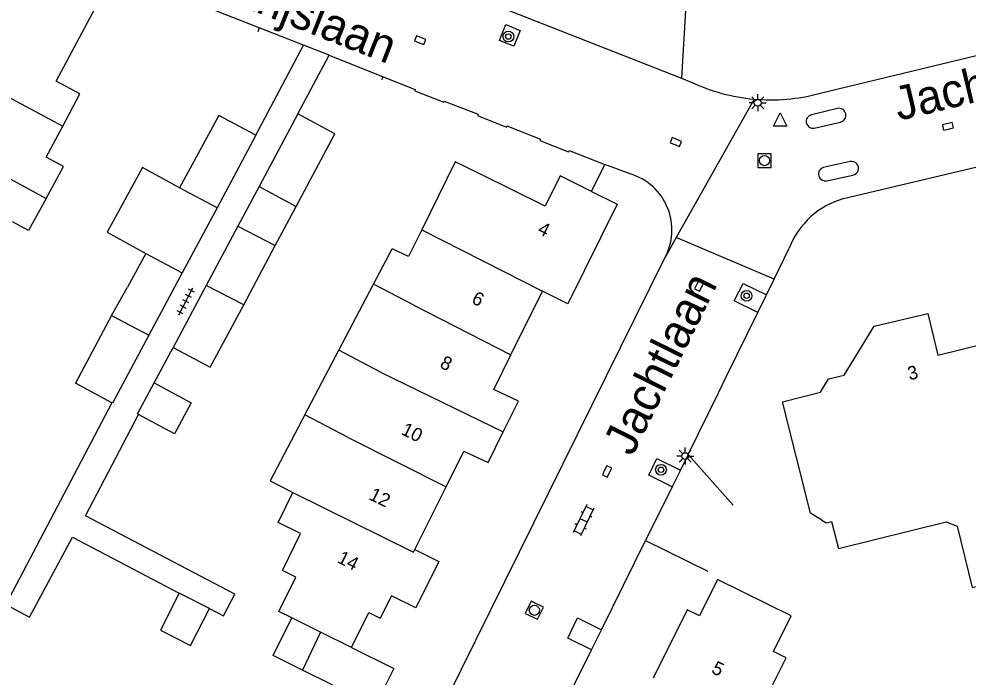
# Model space of a CAD drawing. Extents: x 136000 to 141000, y 400494 to 402006.
# Drawn here: x 137841.5 to 137911.7, y 401638.7 to 401687.4 of the extents above; entities that cross this region are included whole.
import ezdxf

# ---------------------------------------------------------------- set-up
doc = ezdxf.new("R2010")
doc.units = 0
for name, color, linetype in [('gg-afsc-erfafscheiding', 7, 'Continuous'), ('gg-afsc-muur', 7, 'Continuous'), ('gg-anno-huisnummerreeks BGT', 7, 'Continuous'), ('gg-anno-openbare ruimte label', 7, 'Continuous'), ('gg-bbg-bijgebouw', 7, 'Continuous'), ('gg-bbg-gedigitaliseerde bebouwing', 7, 'Continuous'), ('gg-bbg-gedigitaliseerde bijgebouw', 7, 'Continuous'), ('gg-bbg-hoofdgebouw', 7, 'Continuous'), ('gg-bbg-tussenscheiding', 7, 'Continuous'), ('gg-knt-verharding', 7, 'Continuous'), ('gt-grn-weggrens', 7, 'Continuous'), ('gt-symb-boom', 7, 'Continuous'), ('gt-symb-klinker verharding', 7, 'Continuous'), ('gt-symb-kolk', 7, 'Continuous'), ('gt-symb-lichtmast', 7, 'Continuous'), ('gt-symb-rioolschacht', 7, 'Continuous'), ('gt-symb-tegel verharding', 7, 'Continuous'), ('gt-symb-waterafsluiter', 7, 'Continuous')]:
    doc.layers.add(name, color=color, linetype=linetype)

# ---------------------------------------------------------------- blocks, each defined once
blk = doc.blocks.new('gt0-KOLK')
at = {"layer": 'gt-symb-kolk'}
blk.add_lwpolyline([(0, 0), (0.375, 0), (0.375, 0.4), (-0.375, 0.4), (-0.375, 0), (0, 0)], dxfattribs=at)
blk = doc.blocks.new('gt0-BOOM')
at = {"layer": 'gt-symb-boom'}
for radius in [0.4, 0.2]:
    blk.add_circle((0, 0), radius, dxfattribs=at)
blk = doc.blocks.new('gt0-LMAST')
at = {"layer": 'gt-symb-lichtmast'}
for p, q in [((-0.182, 0.173), (-0.447, 0.438)), ((-0.005, 0.246), (-0.005, 0.621)), ((0.172, 0.173), (0.437, 0.438)), ((-0.255, -0.004), (-0.63, -0.004)), ((-0.182, -0.181), (-0.447, -0.446)), ((-0.005, -0.254), (-0.005, -0.629)), ((0.437, -0.446), (0.172, -0.181)), ((0.245, -0.004), (0.62, -0.004))]:
    blk.add_line(p, q, dxfattribs=at)
blk.add_circle((-0.005, -0.004), 0.25, dxfattribs=at)
blk = doc.blocks.new('gt0-RS')
at = {"layer": 'gt-symb-rioolschacht'}
blk.add_lwpolyline([(-0.5, -0.5), (0.5, -0.5), (0.5, 0.5), (-0.5, 0.5)], close=True, dxfattribs=at)
blk.add_circle((0, 0), 0.375, dxfattribs=at)
blk = doc.blocks.new('gt0-WAFSL')
at = {"layer": 'gt-symb-waterafsluiter'}
for p, q in [((-0.5, -0.333), (0, 0.667)), ((0, 0.667), (0.5, -0.333)), ((0.5, -0.333), (-0.5, -0.333))]:
    blk.add_line(p, q, dxfattribs=at)
blk = doc.blocks.new('gt0-TEG1')
at = {"layer": 'gt-symb-tegel verharding'}
for p, q in [((-1.125, 0), (1.125, 0)), ((-0.9, -0.25), (-0.9, 0.25)), ((-0.45, -0.25), (-0.45, 0.25)), ((0, -0.25), (0, 0.25)), ((0.45, -0.25), (0.45, 0.25)), ((0.9, -0.25), (0.9, 0.25))]:
    blk.add_line(p, q, dxfattribs=at)
blk = doc.blocks.new('gt0-KL1')
at = {"layer": 'gt-symb-klinker verharding'}
for p, q in [((-1.15, 0.3), (1.15, 0.3)), ((-1, -0.3), (-1, 0.3)), ((-0.5, 0.3), (-0.5, 0.45)), ((0, -0.3), (0, 0.3)), ((0.5, 0.3), (0.5, 0.45)), ((1, -0.3), (1, 0.3)), ((-1.15, -0.3), (1.15, -0.3)), ((-0.5, -0.45), (-0.5, -0.3)), ((0.5, -0.45), (0.5, -0.3))]:
    blk.add_line(p, q, dxfattribs=at)

msp = doc.modelspace()

# ---------------------------------------------------------------- linework, layer by layer
at = {"layer": 'gg-afsc-erfafscheiding'}
for points in [[(137882.227, 401714.91), (137892.182, 401711.001), (137890.525, 401682.979)], [(137848.387, 401658.961), (137840.554, 401644.032), (137842.304, 401643.095), (137845.475, 401649.014), (137853.375, 401644.869)], [(137855.605, 401643.731), (137856.639, 401643.188), (137857.48, 401644.79), (137846.428, 401650.589), (137850.362, 401658.085)]]:
    msp.add_lwpolyline(points, dxfattribs=at)
at = {"layer": 'gg-afsc-muur'}
for p, q in [((137859.293, 401686.702), (137839.536, 401694.481)), ((137859.293, 401686.702), (137859.184, 401686.405)), ((137859.039, 401678.757), (137862.567, 401685.415)), ((137862.139, 401680.33), (137864.457, 401684.672)), ((137864.457, 401684.672), (137868.45, 401683.081)), ((137868.45, 401683.081), (137868.459, 401683.106)), ((137868.378, 401682.873), (137868.45, 401683.081)), ((137868.45, 401683.081), (137870.839, 401682.13)), ((137883.887, 401674.594), (137884.872, 401676.588)), ((137851.509, 401660.425), (137852.921, 401663.059)), ((137891.038, 401655.14), (137890.456, 401653.969)), ((137894.351, 401651.395), (137891.038, 401655.14)), ((137890.456, 401653.969), (137889.85, 401652.751)), ((137889.85, 401652.751), (137887.866, 401648.763)), ((137887.866, 401648.763), (137892.495, 401646.498))]:
    msp.add_line(p, q, dxfattribs=at)
msp.add_lwpolyline([(137870.839, 401682.13), (137870.799, 401682.032), (137872.948, 401681.197), (137872.981, 401681.282), (137875.482, 401680.305), (137875.444, 401680.207), (137877.583, 401679.363), (137877.621, 401679.448), (137880.096, 401678.456), (137880.057, 401678.359), (137882.183, 401677.533), (137882.221, 401677.63), (137884.872, 401676.588)], dxfattribs=at)
at = {"layer": 'gg-bbg-bijgebouw'}
for p, q in [((137862.139, 401680.33), (137859.277, 401674.968)), ((137859.039, 401678.757), (137856.299, 401680.225)), ((137859.039, 401678.757), (137856.169, 401673.396)), ((137859.277, 401674.968), (137857.704, 401672.02)), ((137856.169, 401673.396), (137853.594, 401668.584)), ((137860.479, 401670.591), (137862.017, 401673.474)), ((137857.704, 401672.02), (137855.368, 401667.643)), ((137858.142, 401666.215), (137860.479, 401670.591)), ((137853.594, 401668.584), (137851.115, 401663.952)), ((137855.368, 401667.643), (137852.921, 401663.059)), ((137848.387, 401658.961), (137845.689, 401660.406))]:
    msp.add_line(p, q, dxfattribs=at)
for points in [[(137862.017, 401673.474), (137864.894, 401678.862), (137862.139, 401680.33)], [(137852.921, 401663.059), (137855.673, 401661.59), (137858.142, 401666.215)], [(137851.115, 401663.952), (137848.431, 401658.938), (137848.387, 401658.961)], [(137850.362, 401658.085), (137850.275, 401658.132), (137851.509, 401660.425)], [(137851.509, 401660.425), (137854.256, 401658.946), (137853.022, 401656.653), (137850.362, 401658.085)]]:
    msp.add_lwpolyline(points, dxfattribs=at)
at = {"layer": 'gg-bbg-gedigitaliseerde bebouwing'}
for p, q in [((137844.758, 401679.427), (137846.028, 401681.809)), ((137867.745, 401667.741), (137869.12, 401670.362)), ((137865.177, 401662.846), (137867.745, 401667.741)), ((137862.666, 401658.061), (137865.177, 401662.846)), ((137867.88, 401636.53), (137862.501, 401639.178))]:
    msp.add_line(p, q, dxfattribs=at)
for points in [[(137843.52, 401674.064), (137844.821, 401676.433), (137843.521, 401677.144), (137844.758, 401679.427)], [(137843.52, 401674.064), (137842.219, 401671.695), (137841.025, 401672.351)], [(137900.916, 401650.273), (137901.238, 401650.079), (137901.643, 401650.18), (137902.146, 401648.168), (137910.128, 401650.16), (137910.92, 401649.827), (137912.05, 401645.298), (137916.963, 401646.524), (137912.91, 401663.31)], [(137862.666, 401658.061), (137860.109, 401653.187), (137861.78, 401652.31)], [(137861.697, 401643.052), (137860.753, 401643.52), (137862.009, 401646.056), (137861.004, 401646.554), (137862.354, 401649.28), (137860.688, 401650.105), (137861.78, 401652.31)], [(137899.176, 401633.249), (137899.317, 401633.533), (137897.73, 401634.319), (137898.79, 401636.46), (137896.928, 401637.382), (137898.271, 401640.097), (137897.338, 401640.559), (137898.64, 401643.188), (137893.2, 401645.89)]]:
    msp.add_lwpolyline(points, dxfattribs=at)
at = {"layer": 'gg-bbg-gedigitaliseerde bijgebouw'}
for p, q in [((137856.299, 401680.225), (137853.384, 401674.868)), ((137850.907, 401670.007), (137849.539, 401667.516)), ((137848.355, 401665.426), (137849.539, 401667.516)), ((137848.355, 401665.426), (137845.689, 401660.406)), ((137855.605, 401643.731), (137853.375, 401644.869))]:
    msp.add_line(p, q, dxfattribs=at)
for points in [[(137853.384, 401674.868), (137850.668, 401676.36), (137848.043, 401671.58), (137850.907, 401670.007)], [(137853.375, 401644.869), (137851.985, 401642.144), (137854.215, 401641.006), (137855.605, 401643.731)], [(137862.501, 401639.178), (137860.312, 401640.255), (137861.697, 401643.052)]]:
    msp.add_lwpolyline(points, dxfattribs=at)
at = {"layer": 'gg-bbg-hoofdgebouw'}
for p, q in [((137880.44, 401673.507), (137875.62, 401675.89)), ((137877.919, 401662.5), (137880.245, 401667.214)), ((137870.817, 401648.104), (137873.114, 401652.742)), ((137890.96, 401643.65), (137888.44, 401638.57))]:
    msp.add_line(p, q, dxfattribs=at)
for points in [[(137846.028, 401681.809), (137844.278, 401682.763), (137847.34, 401688.518), (137841.179, 401691.841), (137839.52, 401688.78)], [(137875.62, 401675.89), (137873.787, 401676.785), (137871.317, 401671.763)], [(137883.887, 401674.594), (137881.547, 401675.749), (137880.44, 401673.507)], [(137883.887, 401674.594), (137885.77, 401673.664), (137882.128, 401666.284), (137880.245, 401667.214)], [(137871.317, 401671.763), (137870.342, 401669.78), (137869.12, 401670.362)], [(137900.916, 401650.273), (137900.068, 401650.783), (137898.01, 401659.03), (137900.83, 401659.74), (137901.4, 401660.73), (137902.58, 401661), (137904.8, 401664.62), (137908.77, 401665.57), (137909.51, 401662.49), (137912.91, 401663.31)], [(137877.345, 401656.805), (137878.47, 401659.07), (137876.66, 401659.95), (137877.919, 401662.5)], [(137873.114, 401652.742), (137874.42, 401655.38), (137876.22, 401654.54), (137877.345, 401656.805)], [(137870.817, 401648.104), (137872.583, 401647.223), (137870.869, 401643.787), (137869.082, 401644.662), (137868.243, 401643.023)], [(137893.2, 401645.89), (137891.86, 401643.2), (137890.96, 401643.65)], [(137866.109, 401640.857), (137867.4, 401643.44), (137868.243, 401643.023)], [(137866.109, 401640.857), (137869.24, 401639.3), (137867.88, 401636.53)]]:
    msp.add_lwpolyline(points, dxfattribs=at)
at = {"layer": 'gg-bbg-tussenscheiding'}
for p, q in [((137835.959, 401684.148), (137844.758, 401679.427)), ((137840.594, 401675.671), (137843.52, 401674.064)), ((137856.169, 401673.396), (137853.384, 401674.868)), ((137859.277, 401674.968), (137862.017, 401673.474)), ((137857.704, 401672.02), (137860.479, 401670.591)), ((137871.317, 401671.763), (137880.245, 401667.214)), ((137850.907, 401670.007), (137853.594, 401668.584)), ((137870.721, 401666.18), (137867.745, 401667.741)), ((137858.142, 401666.215), (137855.368, 401667.643)), ((137870.721, 401666.18), (137877.919, 401662.5)), ((137848.355, 401665.426), (137851.115, 401663.952)), ((137868.267, 401661.224), (137865.177, 401662.846)), ((137868.267, 401661.224), (137877.345, 401656.805)), ((137865.869, 401656.38), (137862.666, 401658.061)), ((137865.869, 401656.38), (137873.114, 401652.742)), ((137863.824, 401641.994), (137861.697, 401643.052)), ((137863.824, 401641.994), (137862.501, 401639.178)), ((137866.109, 401640.857), (137863.824, 401641.994))]:
    msp.add_line(p, q, dxfattribs=at)
msp.add_lwpolyline([(137861.78, 401652.31), (137870.718, 401647.904), (137870.817, 401648.104)], dxfattribs=at)
at = {"layer": 'gg-knt-verharding'}
for p, q in [((137859.009, 401695.383), (137890.525, 401682.979)), ((137862.567, 401685.415), (137859.293, 401686.702)), ((137864.457, 401684.672), (137862.567, 401685.415)), ((137890.525, 401682.979), (137891.261, 401682.689)), ((137902.086, 401680.74), (137900.154, 401680.268)), ((137900.359, 401679.286), (137902.31, 401679.733)), ((137902.53, 401674.07), (137922.882, 401678.934)), ((137903.008, 401676.806), (137901.029, 401676.369)), ((137886.73, 401675.9), (137884.872, 401676.588)), ((137901.291, 401675.383), (137903.217, 401675.796)), ((137897.383, 401668.107), (137898.51, 401670.411)), ((137863.73, 401617.96), (137889.28, 401669.641)), ((137896.814, 401666.944), (137897.383, 401668.107)), ((137896.178, 401665.644), (137896.814, 401666.944)), ((137893.871, 401660.93), (137896.178, 401665.644)), ((137893.248, 401659.656), (137893.871, 401660.93)), ((137891.038, 401655.14), (137893.248, 401659.656)), ((137884.607, 401642.165), (137887.866, 401648.763)), ((137883.867, 401640.667), (137884.607, 401642.165)), ((137872.928, 401618.523), (137883.867, 401640.667))]:
    msp.add_line(p, q, dxfattribs=at)
for points in [[(137877.18, 401686.042), (137877.536, 401686.958), (137878.592, 401686.517), (137878.128, 401685.346), (137877.069, 401685.757), (137877.18, 401686.042)], [(137900.7, 401681.84), (137918.809, 401686.207), (137920.955, 401686.767)], [(137896.178, 401665.644), (137894.444, 401666.493), (137895.107, 401667.779), (137896.814, 401666.944)], [(137889.85, 401652.751), (137888.124, 401653.609), (137888.703, 401654.841), (137890.456, 401653.969)], [(137883.867, 401640.667), (137882.116, 401641.532), (137882.848, 401643.034), (137884.607, 401642.165)]]:
    msp.add_lwpolyline(points, dxfattribs=at)
for centre, radius, start, end in [((137897.143, 401695.191), 13.817, 244.80408, 264.85905), ((137897.142, 401695.207), 13.833, 264.86935, 284.90512), ((137902.184, 401680.233), 0.516, 284.11016, 100.97156), ((137900.26, 401679.778), 0.502, 102.24274, 281.34044), ((137903.117, 401676.302), 0.516, 281.21469, 102.1678), ((137901.178, 401675.881), 0.51, 107.01785, 282.74369), ((137885.508, 401671.753), 4.323, 330.75029, 73.58299), ((137904.215, 401668.181), 6.125, 105.96599, 158.65087)]:
    msp.add_arc(centre, radius, start, end, dxfattribs=at)
at = {"layer": 'gt-grn-weggrens'}
for p, q in [((137895.905, 401681.43), (137890.15, 401671.189)), ((137890.15, 401671.189), (137889.28, 401669.641)), ((137897.383, 401668.107), (137890.15, 401671.189))]:
    msp.add_line(p, q, dxfattribs=at)

# ---------------------------------------------------------------- block references
at = {"layer": 'gt-symb-boom'}
for p in [(137877.725, 401686.061), (137895.351, 401666.875), (137889.02, 401654.003)]:
    msp.add_blockref('gt0-BOOM', p, dxfattribs=at)
at = {"layer": 'gt-symb-klinker verharding', "rotation": -115.97571465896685}
msp.add_blockref('gt0-KL1', (137883.287, 401650.271), dxfattribs=at)
at = {"layer": 'gt-symb-kolk'}
for p, rotation in [((137871.131, 401685.598), -21.641900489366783), ((137910.296, 401679.214), 13.480126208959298), ((137890.041, 401678.067), -21.641900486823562), ((137891.676, 401667.732), -116.36005820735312), ((137884.849, 401653.961), -116.36005820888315)]:
    msp.add_blockref('gt0-KOLK', p, dxfattribs=dict(at, rotation=rotation))
at = {"layer": 'gt-symb-lichtmast'}
for p in [(137896.178, 401681.163), (137890.817, 401655.019)]:
    msp.add_blockref('gt0-LMAST', p, dxfattribs=at)
at = {"layer": 'gt-symb-rioolschacht'}
msp.add_blockref('gt0-RS', (137896.677, 401676.879), dxfattribs=at)
at = {"layer": 'gt-symb-rioolschacht', "rotation": 63.716687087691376}
msp.add_blockref('gt0-RS', (137879.65, 401643.605), dxfattribs=at)
at = {"layer": 'gt-symb-tegel verharding', "rotation": 62.564181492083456}
msp.add_blockref('gt0-TEG1', (137853.862, 401666.458), dxfattribs=at)
at = {"layer": 'gt-symb-waterafsluiter'}
msp.add_blockref('gt0-WAFSL', (137897.84, 401679.757), dxfattribs=at)

# ---------------------------------------------------------------- texts
at = {"layer": 'gg-anno-huisnummerreeks BGT'}
for s, rotation, p in [('4', 333.7, (137879.819, 401671.521)), ('6', 333.8, (137874.935, 401666.37)), ('8', 333.7, (137872.585, 401661.607)), ('3', 13.5, (137907.396, 401660.614)), ('10', 333.6, (137869.724, 401656.662)), ('12', 333.6, (137867.339, 401651.845)), ('14', 333.1, (137864.994, 401647.178)), ('5', 333.6, (137892.687, 401639.005))]:
    msp.add_text(s, height=1, rotation=rotation, dxfattribs=at).set_placement(p)
at = {"layer": 'gg-anno-openbare ruimte label'}
for s, rotation, p in [('Patrijslaan', 338.5, (137854.291, 401689.737)), ('Jachtlaan', 13.6, (137906.597, 401679.814)), ('Jachtlaan', 63.7, (137886.891, 401654.923))]:
    msp.add_text(s, height=2.5, rotation=rotation, dxfattribs=at).set_placement(p)

doc.saveas('drawing.dxf')
